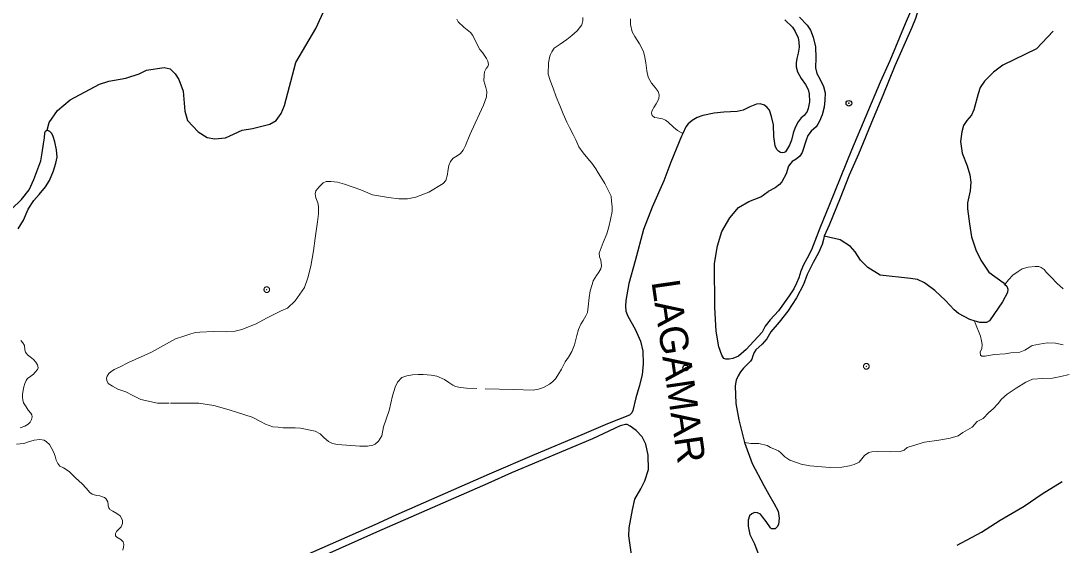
# Model space of a CAD drawing. Extents: x 267.7 to 296, y 7537.7 to 7565.8.
# Drawn here: x 282.305 to 285.983, y 7559.393 to 7561.246 of the extents above; entities that cross this region are included whole.
import ezdxf
from ezdxf.enums import TextEntityAlignment as Align

# ---------------------------------------------------------------- set-up
doc = ezdxf.new("R2010")
doc.units = 0
doc.header["$LTSCALE"] = 0.04
doc.header["$PDMODE"] = 32
doc.header["$PDSIZE"] = 0.02
doc.linetypes.add('SHORT_DASHED', pattern=[2.7, 1.5, -1.2])
for name, color, linetype, lineweight in [('1', 7, 'Continuous', 25), ('2', 7, 'Continuous', 25), ('21', 7, 'SHORT_DASHED', 13), ('7', 7, 'Continuous', 25)]:
    doc.layers.add(name, color=color, linetype=linetype, lineweight=lineweight)
doc.layers.add('54', color=7, linetype='Continuous')
doc.layers.add('61', color=7, linetype='Continuous')

msp = doc.modelspace()

# ---------------------------------------------------------------- linework, layer by layer
at = {"layer": '1'}
for points in [[(285.6145, 7561.7727), (285.587, 7561.6783), (285.5595, 7561.5803), (285.5397, 7561.5137), (285.4984, 7561.37), (285.4808, 7561.3034), (285.4653, 7561.2545), (285.4521, 7561.222), (285.4477, 7561.2121), (285.3927, 7561.0866), (285.3503, 7560.9825), (285.3156, 7560.9005), (285.2639, 7560.7745), (285.2314, 7560.7012), (285.1995, 7560.6192), (285.1598, 7560.5246), (285.1424, 7560.4856)], [(285.4474, 7561.2795), (285.4292, 7561.236), (285.3744, 7561.1048), (285.3405, 7561.0292), (285.2397, 7560.7885), (285.1615, 7560.5965), (285.1268, 7560.513), (285.0981, 7560.4374), (285.0824, 7560.407), (285.0694, 7560.3836), (285.0607, 7560.3618), (285.0529, 7560.3384), (285.0451, 7560.3193), (285.0355, 7560.2993), (285.019, 7560.2749), (284.9808, 7560.2211), (284.9521, 7560.1898), (284.9338, 7560.1672), (284.9234, 7560.1455), (284.8939, 7560.1142), (284.8669, 7560.0846), (284.84, 7560.0612), (284.82, 7560.0525), (284.807, 7560.0507), (284.7948, 7560.0507), (284.7879, 7560.0533)], [(285.1424, 7560.4856), (285.1406, 7560.4739), (285.1356, 7560.4563), (285.123, 7560.4266), (285.1042, 7560.3924), (285.0828, 7560.3501), (285.069, 7560.3143), (285.0453, 7560.2675), (285.0145, 7560.2196), (284.9837, 7560.1816), (284.9545, 7560.1475), (284.9402, 7560.1227), (284.9231, 7560.1035), (284.9011, 7560.0831), (284.8951, 7560.0743), (284.8907, 7560.0622), (284.8868, 7560.0506), (284.8824, 7560.044), (284.8758, 7560.0369), (284.8676, 7560.028), (284.8571, 7560.0192), (284.8472, 7560.0055), (284.8384, 7559.9917), (284.8318, 7559.9758), (284.8285, 7559.9559)], [(284.4547, 7559.8523), (284.377, 7559.8218), (284.2867, 7559.7831), (284.1184, 7559.7122), (283.9591, 7559.6438), (283.6289, 7559.4987), (283.5547, 7559.465), (283.1514, 7559.2873), (283.0583, 7559.2484), (282.7675, 7559.1216), (282.6934, 7559.0875), (282.5888, 7559.0438), (282.5414, 7559.0202), (282.4852, 7558.9986), (282.4399, 7558.9791), (282.4346, 7558.9766)], [(284.4569, 7559.8141), (284.4466, 7559.8195), (284.4404, 7559.8202), (284.422, 7559.8154), (284.324, 7559.7695), (284.0384, 7559.6483), (283.9549, 7559.6106), (283.5617, 7559.4394), (283.3631, 7559.3504), (282.9624, 7559.1771), (282.7741, 7559.0929), (282.5289, 7558.986), (282.4844, 7558.9668), (282.4686, 7558.9579), (282.4549, 7558.949), (282.4152, 7558.9223), (282.3734, 7558.8977), (282.3501, 7558.8792), (282.3251, 7558.8643)]]:
    msp.add_lwpolyline(points, dxfattribs=at)
at = {"layer": '2'}
for points in [[(285.0555, 7561.2592), (285.0828, 7561.2312), (285.0942, 7561.213), (285.104, 7561.1887), (285.1124, 7561.1546), (285.1131, 7561.1159), (285.1124, 7561.0795), (285.1162, 7561.0605), (285.1268, 7561.0415), (285.1404, 7561.0135), (285.1465, 7560.9915), (285.145, 7560.9657), (285.142, 7560.9414), (285.1359, 7560.9141), (285.126, 7560.8913), (285.1207, 7560.8807), (285.1139, 7560.8716), (285.0972, 7560.8557), (285.0843, 7560.8405), (285.079, 7560.8246), (285.0654, 7560.7813), (285.0562, 7560.7684), (285.0441, 7560.7578), (285.0297, 7560.7487), (285.0244, 7560.7434), (285.0168, 7560.7328), (285.0085, 7560.7055), (284.9933, 7560.6774), (284.9849, 7560.6676), (284.969, 7560.6554), (284.9447, 7560.6425)], [(285.0039, 7561.2494), (285.0305, 7561.2243), (285.0403, 7561.2084), (285.0502, 7561.1857), (285.0532, 7561.1705), (285.054, 7561.153), (285.0509, 7561.1318), (285.0464, 7561.1128), (285.0434, 7561.0977), (285.0434, 7561.084), (285.0479, 7561.0658), (285.0608, 7561.0423), (285.0767, 7561.021), (285.0858, 7561.0036), (285.0896, 7560.9884), (285.0904, 7560.9604), (285.0866, 7560.9368), (285.0828, 7560.9262), (285.0714, 7560.9118), (285.0608, 7560.9035), (285.0509, 7560.8898), (285.0396, 7560.8686), (285.0335, 7560.8489), (285.0274, 7560.8246), (285.0206, 7560.8064), (285.01, 7560.7889), (285.0062, 7560.7836), (285.0016, 7560.7806), (284.994, 7560.7791), (284.9887, 7560.7813), (284.9812, 7560.7859), (284.9751, 7560.792)], [(284.9751, 7560.792), (284.9699, 7560.8042), (284.965, 7560.8369), (284.964, 7560.8786), (284.957, 7560.9083), (284.9491, 7560.9301), (284.9411, 7560.9401), (284.9322, 7560.948), (284.9163, 7560.953), (284.9034, 7560.952), (284.8796, 7560.942), (284.8568, 7560.9301), (284.835, 7560.9252), (284.7884, 7560.9232), (284.7536, 7560.9202), (284.714, 7560.9113), (284.6941, 7560.9044), (284.6763, 7560.8944), (284.6624, 7560.8825), (284.6534, 7560.8716), (284.6429, 7560.8484)], [(282.2958, 7560.5111), (282.3138, 7560.5413), (282.331, 7560.5808), (282.3512, 7560.611), (282.3699, 7560.6326), (282.3922, 7560.6592), (282.4058, 7560.6822), (282.4202, 7560.716), (282.4288, 7560.7433), (282.4331, 7560.7649), (282.4303, 7560.7908), (282.4245, 7560.8188), (282.4188, 7560.8375), (282.4145, 7560.8483), (282.4073, 7560.8555), (282.3979, 7560.8601)], [(282.3505, 7560.6851), (282.3749, 7560.7519), (282.3799, 7560.7793), (282.385, 7560.8116), (282.3878, 7560.8332), (282.3893, 7560.8504)], [(282.3893, 7560.8504), (282.3914, 7560.8562), (282.3965, 7560.8598), (282.3979, 7560.8601)], [(284.6429, 7560.8484), (284.6386, 7560.8389), (284.6009, 7560.7466), (284.5761, 7560.6811), (284.5344, 7560.5879), (284.5046, 7560.5085), (284.4749, 7560.3984), (284.453, 7560.318), (284.4421, 7560.2575), (284.4411, 7560.2377), (284.4421, 7560.2198), (284.4491, 7560.202), (284.4749, 7560.1563), (284.4937, 7560.1147), (284.5017, 7560.079), (284.5036, 7560.0343), (284.4997, 7559.9946), (284.4888, 7559.954), (284.4778, 7559.9133), (284.4669, 7559.8696), (284.463, 7559.8607), (284.4547, 7559.8523)], [(282.2721, 7560.5801), (282.3073, 7560.6146), (282.3346, 7560.6491), (282.3505, 7560.6851)], [(284.7879, 7560.0533), (284.7814, 7560.0641), (284.7705, 7560.0938), (284.7606, 7560.1494), (284.7566, 7560.2327), (284.7546, 7560.3885), (284.7655, 7560.451), (284.7814, 7560.5016), (284.8092, 7560.5502), (284.84, 7560.5859), (284.8767, 7560.6077), (284.9183, 7560.6236), (284.9447, 7560.6425)], [(284.8285, 7559.9559), (284.83, 7559.8944), (284.8409, 7559.8359), (284.8608, 7559.7555)], [(284.4677, 7559.3423), (284.463, 7559.3528), (284.458, 7559.3845), (284.4521, 7559.4262), (284.454, 7559.454), (284.465, 7559.5184), (284.4739, 7559.5561), (284.4947, 7559.5928), (284.5096, 7559.6206), (284.5215, 7559.6603), (284.5205, 7559.7109), (284.5126, 7559.7496), (284.4997, 7559.7764), (284.4788, 7559.7982), (284.4569, 7559.8141)], [(284.8608, 7559.7555), (284.8886, 7559.6821), (284.9292, 7559.6038), (284.9471, 7559.572), (284.965, 7559.5422), (284.9798, 7559.5135), (284.9838, 7559.4887), (284.9808, 7559.4659), (284.9769, 7559.4579), (284.9699, 7559.451), (284.965, 7559.451), (284.957, 7559.451), (284.953, 7559.4549), (284.9382, 7559.4768), (284.9253, 7559.4936), (284.9173, 7559.5026), (284.9074, 7559.5075), (284.8965, 7559.5085), (284.8866, 7559.5045), (284.8786, 7559.4966), (284.8737, 7559.4817), (284.8737, 7559.4609), (284.8796, 7559.4311), (284.8965, 7559.3974), (284.9153, 7559.3478)], [(285.6129, 7559.3928), (285.6984, 7559.4396), (285.7645, 7559.4811), (285.8494, 7559.5309), (285.9131, 7559.5742), (285.9839, 7559.6181)]]:
    msp.add_lwpolyline(points, dxfattribs=at)
msp.add_point((284.6534, 7560.0196), dxfattribs=at)
at = {"layer": '21'}
for points in [[(282.7879, 7559.8954), (282.7284, 7559.908), (282.7032, 7559.9206), (282.6755, 7559.9348), (282.647, 7559.9449), (282.6285, 7559.955), (282.6134, 7559.965), (282.6084, 7559.9751), (282.6076, 7559.9835), (282.6092, 7559.9902), (282.616, 7559.9994), (282.6227, 7560.0053), (282.6344, 7560.0137), (282.6529, 7560.0221), (282.6847, 7560.0388), (282.7661, 7560.0749), (282.8189, 7560.1043), (282.8508, 7560.1227), (282.8802, 7560.1319), (282.9053, 7560.1403), (282.9221, 7560.1445), (282.9372, 7560.1462), (282.9859, 7560.1479), (283.0303, 7560.147), (283.0613, 7560.1496), (283.0857, 7560.1554), (283.136, 7560.1756), (283.1729, 7560.1949), (283.2249, 7560.2209), (283.2467, 7560.2309), (283.2736, 7560.2569), (283.3063, 7560.3039), (283.3189, 7560.3383), (283.3289, 7560.3794), (283.3381, 7560.4331), (283.344, 7560.4784), (283.3532, 7560.5354), (283.3566, 7560.5639), (283.3566, 7560.5899), (283.3541, 7560.6033), (283.3465, 7560.6201), (283.3449, 7560.6352), (283.3465, 7560.6453), (283.3583, 7560.6595), (283.3725, 7560.6738), (283.3834, 7560.678), (283.4002, 7560.6788), (283.4237, 7560.6763), (283.448, 7560.6688), (283.5059, 7560.6486), (283.547, 7560.631), (283.604, 7560.6218), (283.6401, 7560.6168), (283.6711, 7560.6168), (283.7005, 7560.6226), (283.7458, 7560.6411), (283.797, 7560.6713), (283.8062, 7560.6822), (283.8121, 7560.7032), (283.8129, 7560.7149), (283.8171, 7560.735), (283.823, 7560.7493), (283.8322, 7560.761), (283.8456, 7560.7686), (283.8582, 7560.777), (283.8674, 7560.7895), (283.875, 7560.8055), (283.8909, 7560.8432), (283.9093, 7560.8843), (283.9253, 7560.917), (283.9395, 7560.9481), (283.9496, 7560.9774), (283.9513, 7560.9967), (283.9479, 7561.011), (283.9404, 7561.0345), (283.9412, 7561.0538), (283.9429, 7561.0655), (283.9488, 7561.0772), (283.9546, 7561.0848), (283.9563, 7561.0923), (283.9546, 7561.1032), (283.9496, 7561.1133), (283.9421, 7561.1242), (283.9354, 7561.1343), (283.9261, 7561.1443), (283.9144, 7561.1678), (283.9018, 7561.1947), (283.8934, 7561.2047), (283.8691, 7561.2232), (283.8498, 7561.2425), (283.8448, 7561.2526)], [(284.2902, 7561.2584), (284.2902, 7561.2458), (284.2868, 7561.2324), (284.27, 7561.2106), (284.2516, 7561.1938), (284.2331, 7561.1796), (284.2096, 7561.1636), (284.1887, 7561.1494), (284.1803, 7561.136), (284.1761, 7561.1276), (284.1736, 7561.1209), (284.1685, 7561.0982), (284.1677, 7561.0571), (284.1752, 7561.0353), (284.1853, 7561.0076), (284.1954, 7560.9774), (284.2088, 7560.9472), (284.2205, 7560.917), (284.234, 7560.8877), (284.2432, 7560.8692), (284.2558, 7560.8441), (284.265, 7560.8256), (284.2759, 7560.8005), (284.2918, 7560.7795), (284.3078, 7560.7594), (284.322, 7560.7434), (284.3354, 7560.7233), (284.3447, 7560.709), (284.3589, 7560.6864), (284.3673, 7560.6713), (284.3799, 7560.6478), (284.39, 7560.626), (284.3916, 7560.6075), (284.3933, 7560.5899), (284.3933, 7560.5723), (284.3883, 7560.5438), (284.3816, 7560.5178), (284.3749, 7560.4935), (284.3614, 7560.4633), (284.348, 7560.4247), (284.3489, 7560.4121), (284.3539, 7560.4004), (284.3564, 7560.3802), (284.3531, 7560.3702), (284.3463, 7560.3576), (284.338, 7560.3458), (284.3271, 7560.3274), (284.3229, 7560.314), (284.3162, 7560.2922), (284.312, 7560.2687), (284.3094, 7560.236), (284.3061, 7560.2158), (284.3011, 7560.2032), (284.291, 7560.1873), (284.2826, 7560.1747), (284.2742, 7560.1554), (284.2683, 7560.1336), (284.2608, 7560.1009), (284.2507, 7560.0774), (284.2398, 7560.0573), (284.2272, 7560.0405), (284.2147, 7560.0154), (284.2021, 7559.9936), (284.1937, 7559.981), (284.1828, 7559.9701), (284.1719, 7559.9617), (284.1509, 7559.9499), (284.1333, 7559.9449), (284.114, 7559.9415), (284.0452, 7559.9432), (283.9161, 7559.9466), (283.8792, 7559.9483), (283.8573, 7559.9499), (283.8397, 7559.9541), (283.8313, 7559.9583), (283.8171, 7559.9675), (283.8011, 7559.9785), (283.7743, 7559.9902), (283.7542, 7559.9944), (283.7265, 7559.9961), (283.708, 7559.9961), (283.6879, 7559.9952), (283.6678, 7559.9919), (283.651, 7559.9852), (283.6359, 7559.9692)], [(284.4579, 7561.2534), (284.4579, 7561.2333), (284.4638, 7561.2073), (284.4738, 7561.1913), (284.4898, 7561.1645), (284.5007, 7561.1452), (284.5049, 7561.136), (284.5082, 7561.1234), (284.5124, 7561.0974), (284.5158, 7561.0697), (284.5208, 7561.0471), (284.5326, 7561.0261), (284.546, 7561.011), (284.556, 7560.9959), (284.5602, 7560.985), (284.5586, 7560.9707), (284.5493, 7560.9531), (284.5409, 7560.9397), (284.5384, 7560.9347), (284.5334, 7560.9271), (284.5326, 7560.9196), (284.5351, 7560.912), (284.5435, 7560.9045), (284.5527, 7560.9036), (284.5644, 7560.9011), (284.572, 7560.8994), (284.582, 7560.8952), (284.5913, 7560.8877), (284.6106, 7560.8701), (284.6248, 7560.8583), (284.6429, 7560.8484)], [(285.7812, 7560.3147), (285.7937, 7560.3308), (285.8091, 7560.3469), (285.8284, 7560.3608), (285.8415, 7560.3693), (285.8638, 7560.3754), (285.8885, 7560.3785), (285.9008, 7560.3777), (285.9092, 7560.3739), (285.9193, 7560.367), (285.9285, 7560.3569), (285.9439, 7560.3408), (285.9639, 7560.3192), (285.9863, 7560.2992)], [(285.987, 7560.1013), (285.9598, 7560.1074), (285.931, 7560.108), (285.916, 7560.1063), (285.8777, 7560.0991), (285.8705, 7560.0946), (285.8517, 7560.0819), (285.8333, 7560.0752), (285.8023, 7560.073), (285.7823, 7560.0697), (285.7429, 7560.0669), (285.7113, 7560.0614), (285.6996, 7560.0614), (285.6952, 7560.0652), (285.6941, 7560.0747), (285.6991, 7560.0885), (285.7008, 7560.1019), (285.6985, 7560.1152), (285.6952, 7560.1318), (285.688, 7560.149), (285.6813, 7560.164), (285.6758, 7560.1784), (285.6724, 7560.1864)], [(282.3027, 7559.8076), (282.3187, 7559.8133), (282.3307, 7559.8213), (282.3381, 7559.8281), (282.3427, 7559.8378), (282.3444, 7559.8464), (282.3438, 7559.8533), (282.3398, 7559.8595), (282.3307, 7559.8704), (282.3233, 7559.8818), (282.3141, 7559.8967), (282.3119, 7559.9069), (282.3101, 7559.9161), (282.3107, 7559.9252), (282.3124, 7559.9407), (282.3159, 7559.9526), (282.3193, 7559.9646), (282.3238, 7559.9749), (282.3284, 7559.9824), (282.3398, 7559.9909), (282.349, 7559.9972), (282.3558, 7560.0041), (282.3638, 7560.0138), (282.3655, 7560.0195), (282.3633, 7560.0309), (282.3581, 7560.0395), (282.3496, 7560.0492), (282.3376, 7560.0589), (282.3278, 7560.0657), (282.321, 7560.0749), (282.3193, 7560.084), (282.3181, 7560.0983), (282.3113, 7560.1086), (282.3044, 7560.1166)], [(284.8608, 7559.7555), (284.8836, 7559.7524), (284.9119, 7559.7524), (284.9413, 7559.7457), (284.9524, 7559.7385), (284.9812, 7559.7263), (284.9896, 7559.7196), (285.0034, 7559.7058), (285.0217, 7559.6941), (285.045, 7559.6858), (285.0617, 7559.6791), (285.0922, 7559.673), (285.1626, 7559.668), (285.2048, 7559.6691), (285.232, 7559.6741), (285.2486, 7559.6786), (285.2658, 7559.6863), (285.2852, 7559.7096), (285.3008, 7559.7202), (285.3108, 7559.7235), (285.3307, 7559.7246), (285.3757, 7559.723), (285.4112, 7559.7241), (285.425, 7559.7285), (285.4356, 7559.7379), (285.4694, 7559.749), (285.4972, 7559.7574), (285.5482, 7559.7646), (285.5881, 7559.7718), (285.6164, 7559.779), (285.632, 7559.7917), (285.6658, 7559.8106), (285.6825, 7559.83), (285.7046, 7559.8406), (285.7246, 7559.8616), (285.7396, 7559.8755), (285.7568, 7559.8938), (285.7695, 7559.9088), (285.789, 7559.9271), (285.8211, 7559.9482), (285.855, 7559.9693), (285.8788, 7559.9798), (285.9154, 7559.9826), (285.9487, 7559.9837), (285.9792, 7559.9887), (286.0086, 7559.9959)], [(283.6359, 7559.9692), (283.6275, 7559.9516), (283.6175, 7559.9214), (283.6057, 7559.8686), (283.5856, 7559.8115), (283.5805, 7559.7797)], [(283.5805, 7559.7797), (283.568, 7559.7604), (283.5562, 7559.7503), (283.5478, 7559.7461), (283.5294, 7559.7436), (283.5017, 7559.7436), (283.4229, 7559.7486), (283.4061, 7559.752), (283.3918, 7559.7595), (283.3767, 7559.7721), (283.3616, 7559.7864), (283.344, 7559.7956), (283.2928, 7559.8065), (283.2736, 7559.8082), (283.2316, 7559.8082), (283.214, 7559.8099), (283.1947, 7559.8115), (283.1687, 7559.8208), (283.1511, 7559.83), (283.1217, 7559.8451), (283.0706, 7559.8619), (283.0404, 7559.8719), (282.9867, 7559.887), (282.933, 7559.8946), (282.829, 7559.8954), (282.7879, 7559.8954)], [(282.6443, 7559.4214), (282.6397, 7559.4266), (282.6386, 7559.43), (282.6392, 7559.4345), (282.6432, 7559.4414), (282.6512, 7559.4494), (282.6592, 7559.4574), (282.6637, 7559.4694), (282.6637, 7559.4802), (282.6609, 7559.4888), (282.6552, 7559.4974), (282.6443, 7559.5048), (282.63, 7559.5128), (282.6197, 7559.5191), (282.6175, 7559.5219), (282.6157, 7559.5254), (282.6135, 7559.5322), (282.6135, 7559.5362), (282.6117, 7559.5465), (282.6049, 7559.5585), (282.5998, 7559.5619), (282.5843, 7559.5676), (282.5729, 7559.5688), (282.5643, 7559.5711), (282.5569, 7559.5739), (282.5489, 7559.5791), (282.5352, 7559.5951), (282.5215, 7559.6099), (282.4975, 7559.6316), (282.4752, 7559.6539), (282.4558, 7559.667), (282.4427, 7559.6727), (282.4352, 7559.6819), (282.4301, 7559.6933), (282.4261, 7559.7082), (282.4198, 7559.7236), (282.4124, 7559.7384), (282.4055, 7559.7493), (282.3958, 7559.7579), (282.3873, 7559.7647), (282.3718, 7559.7664), (282.3518, 7559.7647), (282.3318, 7559.7579), (282.3159, 7559.7527), (282.289, 7559.7499)], [(282.6654, 7559.3751), (282.6672, 7559.3866), (282.6683, 7559.3951), (282.666, 7559.4048), (282.658, 7559.4134), (282.6443, 7559.4214)]]:
    msp.add_lwpolyline(points, dxfattribs=at)
for p in [(283.1736, 7560.2962), (285.2916, 7560.0252)]:
    msp.add_point(p, dxfattribs=at)
at = {"layer": '54'}
msp.add_point((285.2299, 7560.9547), dxfattribs=at)
at = {"layer": '7'}
for points in [[(282.3979, 7560.8601), (282.4051, 7560.8864), (282.4346, 7560.9296), (282.4785, 7560.9669), (282.5823, 7561.0219), (282.6158, 7561.0327), (282.6761, 7561.0431), (282.7231, 7561.0586), (282.7482, 7561.0721), (282.8114, 7561.0812), (282.8324, 7561.0764), (282.8505, 7561.0587), (282.8628, 7561.0389), (282.8787, 7560.998), (282.8836, 7560.9274), (282.8931, 7560.8944), (282.9317, 7560.8534), (282.9631, 7560.8338), (282.9906, 7560.8291), (283.028, 7560.8326), (283.087, 7560.8601), (283.1231, 7560.8657), (283.1849, 7560.881), (283.2062, 7560.8935), (283.2242, 7560.9182), (283.2366, 7560.9468), (283.2756, 7561.0988), (283.3464, 7561.2187), (283.3797, 7561.2905)], [(285.9516, 7561.2092), (285.8923, 7561.1474), (285.7735, 7561.0898), (285.741, 7561.0653), (285.7088, 7561.0327), (285.6936, 7561.0109), (285.6862, 7560.9885), (285.6708, 7560.9311), (285.6636, 7560.9128), (285.6466, 7560.8943), (285.6353, 7560.8762), (285.6293, 7560.854), (285.6236, 7560.8192), (285.6302, 7560.7781), (285.6472, 7560.734), (285.6567, 7560.7016), (285.6606, 7560.6755), (285.6585, 7560.6457), (285.6494, 7560.6025), (285.6493, 7560.5821), (285.6554, 7560.5287), (285.663, 7560.4824), (285.6788, 7560.4367), (285.6961, 7560.4), (285.7247, 7560.3576), (285.7745, 7560.3214), (285.7812, 7560.3147)], [(285.6724, 7560.1864), (285.6575, 7560.191), (285.6177, 7560.2116), (285.6014, 7560.2243), (285.5707, 7560.2583), (285.5333, 7560.2937), (285.4974, 7560.3203), (285.4717, 7560.3316), (285.4471, 7560.3352), (285.3408, 7560.347), (285.2969, 7560.3749), (285.2705, 7560.4007), (285.2516, 7560.4298), (285.2353, 7560.4484), (285.1993, 7560.4722), (285.1424, 7560.4856)], [(285.7812, 7560.3147), (285.7878, 7560.308), (285.7909, 7560.2978), (285.7899, 7560.2865), (285.7731, 7560.2535), (285.7269, 7560.1863), (285.7155, 7560.18), (285.693, 7560.1801), (285.6724, 7560.1864)]]:
    msp.add_lwpolyline(points, dxfattribs=at)

# ---------------------------------------------------------------- texts
at = {"layer": '61'}
msp.add_text('LAGAMAR', height=0.1, rotation=278.286, dxfattribs=at).set_placement((284.5792, 7560.0006), align=Align.CENTER)

doc.saveas('drawing.dxf')
